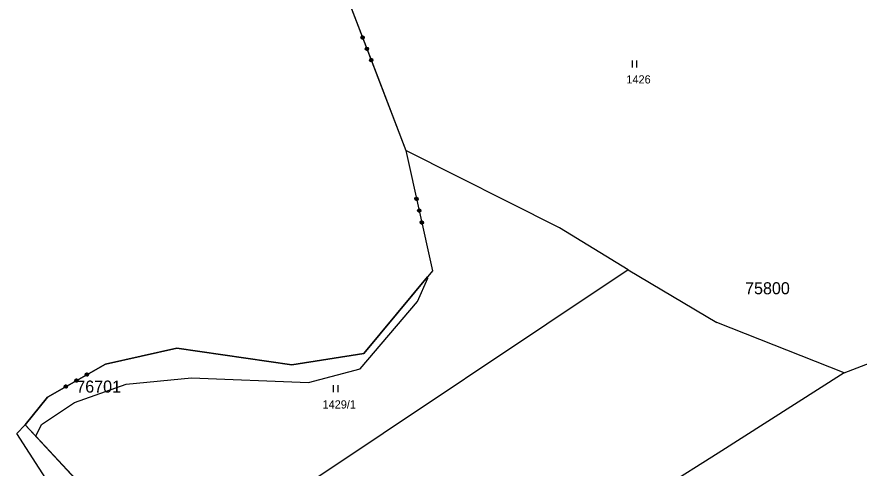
# Model space of a CAD drawing. Extents: x -779618 to -776429, y -1144546 to -1143350.
# Drawn here: x -779593.3 to -779418.1, y -1143790.9 to -1143697.1 of the extents above; entities that cross this region are included whole.
import ezdxf

# ---------------------------------------------------------------- set-up
doc = ezdxf.new("R2010")
doc.units = 0
for name, color, linetype in [('1', 7, 'Continuous'), ('11', 7, 'Continuous'), ('2', 7, 'Continuous'), ('3', 7, 'Continuous')]:
    doc.layers.add(name, color=color, linetype=linetype)

msp = doc.modelspace()

# ---------------------------------------------------------------- linework, layer by layer
at = {"layer": '1'}
for p, q in [((-779528.56, -1143682.63), (-779512.43, -1143724.88)), ((-779480.43, -1143740.94), (-779512.43, -1143724.88)), ((-779512.43, -1143724.88), (-779506.83, -1143749.88)), ((-779466.19, -1143749.69), (-779480.43, -1143740.94)), ((-779466.19, -1143749.69), (-779546.59, -1143803.31)), ((-779506.83, -1143749.88), (-779521.1, -1143767.04)), ((-779466.19, -1143749.69), (-779447.77, -1143760.62)), ((-779421.27, -1143771.11), (-779389.13, -1143758.58)), ((-779421.27, -1143771.11), (-779447.77, -1143760.62)), ((-779560.03, -1143765.93), (-779574.88, -1143769.27)), ((-779536.13, -1143769.42), (-779560.03, -1143765.93)), ((-779521.1, -1143767.04), (-779536.13, -1143769.42)), ((-779574.88, -1143769.27), (-779586.91, -1143776.12)), ((-779421.27, -1143771.11), (-779447.46, -1143787.76)), ((-779586.91, -1143776.12), (-779591.55, -1143781.9)), ((-779591.55, -1143781.9), (-779593.28, -1143783.67)), ((-779591.55, -1143781.9), (-779578.19, -1143796.25)), ((-779576.28, -1143809.92), (-779593.28, -1143783.67)), ((-779447.46, -1143787.76), (-779536.47, -1143843.65))]:
    msp.add_line(p, q, dxfattribs=at)
for points in [[(-779521.04, -1143701.43), (-779521.15, -1143701.67), (-779521.4, -1143701.77), (-779521.65, -1143701.66), (-779521.74, -1143701.41), (-779521.63, -1143701.16), (-779521.38, -1143701.06), (-779521.14, -1143701.17), (-779521.04, -1143701.43), (-779521.07, -1143701.45), (-779521.16, -1143701.23), (-779521.26, -1143701.18), (-779521.12, -1143701.55), (-779521.17, -1143701.64), (-779521.37, -1143701.13), (-779521.44, -1143701.16), (-779521.25, -1143701.66), (-779521.32, -1143701.7), (-779521.51, -1143701.2), (-779521.59, -1143701.23), (-779521.4, -1143701.72), (-779521.49, -1143701.71), (-779521.64, -1143701.3), (-779521.69, -1143701.4), (-779521.59, -1143701.66)], [(-779520.15, -1143703.77), (-779520.26, -1143704.02), (-779520.51, -1143704.11), (-779520.75, -1143704), (-779520.85, -1143703.75), (-779520.74, -1143703.51), (-779520.49, -1143703.41), (-779520.24, -1143703.52), (-779520.15, -1143703.77), (-779520.19, -1143703.78), (-779520.27, -1143703.55), (-779520.38, -1143703.51), (-779520.23, -1143703.88), (-779520.28, -1143703.98), (-779520.48, -1143703.46), (-779520.55, -1143703.49), (-779520.35, -1143704.01), (-779520.43, -1143704.04), (-779520.63, -1143703.52), (-779520.7, -1143703.55), (-779520.5, -1143704.07), (-779520.61, -1143704.02), (-779520.75, -1143703.65), (-779520.8, -1143703.75), (-779520.71, -1143703.98)], [(-779519.25, -1143706.12), (-779519.36, -1143706.36), (-779519.61, -1143706.46), (-779519.86, -1143706.35), (-779519.95, -1143706.1), (-779519.84, -1143705.85), (-779519.59, -1143705.75), (-779519.35, -1143705.86), (-779519.25, -1143706.12), (-779519.3, -1143706.09), (-779519.39, -1143705.87), (-779519.48, -1143705.84), (-779519.35, -1143706.2), (-779519.4, -1143706.3), (-779519.58, -1143705.81), (-779519.66, -1143705.84), (-779519.47, -1143706.33), (-779519.54, -1143706.36), (-779519.73, -1143705.87), (-779519.81, -1143705.89), (-779519.62, -1143706.38), (-779519.71, -1143706.37), (-779519.86, -1143705.98), (-779519.92, -1143706.06), (-779519.83, -1143706.28)], [(-779509.84, -1143735), (-779509.98, -1143735.22), (-779510.24, -1143735.28), (-779510.47, -1143735.14), (-779510.53, -1143734.88), (-779510.39, -1143734.65), (-779510.12, -1143734.59), (-779509.9, -1143734.73), (-779509.84, -1143735), (-779509.87, -1143735.02), (-779509.93, -1143734.78), (-779510.02, -1143734.72), (-779509.93, -1143735.11), (-779510, -1143735.19), (-779510.12, -1143734.66), (-779510.19, -1143734.68), (-779510.08, -1143735.2), (-779510.15, -1143735.22), (-779510.27, -1143734.71), (-779510.35, -1143734.72), (-779510.23, -1143735.24), (-779510.32, -1143735.21), (-779510.42, -1143734.79), (-779510.48, -1143734.88), (-779510.42, -1143735.15)], [(-779509.29, -1143737.45), (-779509.43, -1143737.67), (-779509.69, -1143737.73), (-779509.92, -1143737.59), (-779509.98, -1143737.33), (-779509.84, -1143737.1), (-779509.57, -1143737.04), (-779509.35, -1143737.18), (-779509.29, -1143737.45), (-779509.33, -1143737.45), (-779509.38, -1143737.21), (-779509.48, -1143737.15), (-779509.39, -1143737.54), (-779509.45, -1143737.64), (-779509.57, -1143737.09), (-779509.65, -1143737.11), (-779509.53, -1143737.65), (-779509.61, -1143737.67), (-779509.73, -1143737.13), (-779509.81, -1143737.14), (-779509.68, -1143737.69), (-779509.78, -1143737.63), (-779509.87, -1143737.24), (-779509.93, -1143737.33), (-779509.87, -1143737.57)], [(-779508.74, -1143739.9), (-779508.88, -1143740.12), (-779509.15, -1143740.18), (-779509.37, -1143740.04), (-779509.43, -1143739.77), (-779509.29, -1143739.55), (-779509.02, -1143739.49), (-779508.8, -1143739.63), (-779508.74, -1143739.9), (-779508.79, -1143739.87), (-779508.84, -1143739.63), (-779508.93, -1143739.59), (-779508.85, -1143739.96), (-779508.91, -1143740.06), (-779509.02, -1143739.55), (-779509.1, -1143739.57), (-779508.98, -1143740.07), (-779509.06, -1143740.09), (-779509.18, -1143739.58), (-779509.26, -1143739.59), (-779509.14, -1143740.1), (-779509.23, -1143740.08), (-779509.32, -1143739.68), (-779509.39, -1143739.74), (-779509.33, -1143739.98)], [(-779578.68, -1143771.8), (-779578.94, -1143771.73), (-779579.07, -1143771.5), (-779579, -1143771.24), (-779578.76, -1143771.1), (-779578.5, -1143771.17), (-779578.37, -1143771.41), (-779578.44, -1143771.67), (-779578.68, -1143771.8), (-779578.71, -1143771.77), (-779578.5, -1143771.65), (-779578.47, -1143771.54), (-779578.81, -1143771.74), (-779578.91, -1143771.7), (-779578.44, -1143771.43), (-779578.48, -1143771.36), (-779578.94, -1143771.63), (-779578.99, -1143771.56), (-779578.52, -1143771.3), (-779578.56, -1143771.23), (-779579.02, -1143771.49), (-779579.02, -1143771.4), (-779578.65, -1143771.19), (-779578.75, -1143771.15), (-779578.99, -1143771.29)], [(-779583.04, -1143774.28), (-779583.3, -1143774.21), (-779583.43, -1143773.98), (-779583.36, -1143773.72), (-779583.13, -1143773.59), (-779582.87, -1143773.66), (-779582.73, -1143773.89), (-779582.81, -1143774.15), (-779583.04, -1143774.28), (-779583.02, -1143774.23), (-779582.82, -1143774.11), (-779582.8, -1143774.01), (-779583.13, -1143774.2), (-779583.24, -1143774.17), (-779582.79, -1143773.91), (-779582.83, -1143773.84), (-779583.28, -1143774.1), (-779583.32, -1143774.03), (-779582.87, -1143773.77), (-779582.9, -1143773.7), (-779583.35, -1143773.96), (-779583.36, -1143773.87), (-779583, -1143773.66), (-779583.08, -1143773.62), (-779583.29, -1143773.74)], [(-779580.86, -1143773.04), (-779581.12, -1143772.97), (-779581.25, -1143772.74), (-779581.18, -1143772.48), (-779580.95, -1143772.34), (-779580.69, -1143772.42), (-779580.55, -1143772.65), (-779580.62, -1143772.91), (-779580.86, -1143773.04), (-779580.87, -1143773), (-779580.66, -1143772.88), (-779580.63, -1143772.77), (-779580.98, -1143772.97), (-779581.09, -1143772.94), (-779580.6, -1143772.67), (-779580.64, -1143772.6), (-779581.13, -1143772.87), (-779581.17, -1143772.8), (-779580.68, -1143772.53), (-779580.72, -1143772.46), (-779581.21, -1143772.73), (-779581.18, -1143772.63), (-779580.83, -1143772.43), (-779580.94, -1143772.4), (-779581.15, -1143772.52)]]:
    msp.add_lwpolyline(points, dxfattribs=at)
at = {"layer": '11'}
msp.add_line((-779591.55, -1143781.9), (-779589.34, -1143784.27), dxfattribs=at)
for points in [[(-779539.64, -1143677.6), (-779528.56, -1143682.63), (-779526.17, -1143688.88), (-779518.24, -1143709.67), (-779512.43, -1143724.88), (-779506.83, -1143749.88), (-779507.88, -1143751.15)], [(-779591.55, -1143781.9), (-779586.91, -1143776.12), (-779574.88, -1143769.27), (-779560.03, -1143765.93), (-779536.13, -1143769.42), (-779521.1, -1143767.04), (-779507.88, -1143751.15)], [(-779589.34, -1143784.27), (-779588.16, -1143781.84), (-779581.28, -1143777.25), (-779570.58, -1143773.46), (-779556.94, -1143772.16), (-779532.62, -1143773.12), (-779521.88, -1143770.29), (-779509.95, -1143756.27), (-779507.84, -1143751.41), (-779507.88, -1143751.15)], [(-779589.34, -1143784.27), (-779578.19, -1143796.25), (-779566.83, -1143810.58), (-779564.27, -1143814.83), (-779561.05, -1143820.16), (-779557.13, -1143835.59), (-779551.99, -1143853.39), (-779549.41, -1143860.12), (-779544.64, -1143865.48), (-779537.18, -1143873.87), (-779523.72, -1143881.94), (-779522.52, -1143882.67), (-779506.5, -1143888.29), (-779497.12, -1143891.58), (-779481.42, -1143898.66), (-779468.75, -1143904.38), (-779446.22, -1143922.44), (-779445.96, -1143922.85), (-779432.16, -1143945.16)]]:
    msp.add_lwpolyline(points, dxfattribs=at)
at = {"layer": '3'}
for p, q in [((-779465.34, -1143706.17), (-779465.34, -1143707.67)), ((-779464.34, -1143707.67), (-779464.34, -1143706.17)), ((-779527.48, -1143773.63), (-779527.48, -1143775.13)), ((-779526.48, -1143775.13), (-779526.48, -1143773.63))]:
    msp.add_line(p, q, dxfattribs=at)

# ---------------------------------------------------------------- texts
at = {"layer": '11'}
for s, p in [('75800', (-779441.86, -1143754.76)), ('76701', (-779580.92, -1143775.19))]:
    msp.add_text(s, height=2.5, dxfattribs=at).set_placement(p)
at = {"layer": '2'}
for s, p in [('1426', (-779466.55, -1143710.97)), ('1429/1', (-779529.72, -1143778.5))]:
    msp.add_text(s, height=1.7, dxfattribs=at).set_placement(p)

doc.saveas('drawing.dxf')
